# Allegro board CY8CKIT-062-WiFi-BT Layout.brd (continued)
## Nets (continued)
BT_REG_ON_P3_4: TP37.1 U1.M6(P3_4) U6.14(BT_REG_ON)
BT_UART_CTS: R202.2 TP42.1 U6.4(BT_UART_CTS)
BT_UART_RTS: R203.2 TP43.1 U6.5(BT_UART_RTS)
BT_UART_RXD: R200.2 TP40.1 U6.2(BT_UART_RXD)
BT_UART_TXD: R201.2 TP41.1 U6.3(BT_UART_TXD)
CAP_BUT0_P8_1: CSB1.3 R61.1
CAP_BUT1_P8_2: CSB2.3 R60.1
CAP_PROX_P8_0: J13.1 J13.2 R63.1 R64.1
CAP_SEG0_P8_3: CSS1.1(0) R53.1
CAP_SEG1_P8_4: CSS1.2(1) R52.1
CAP_SEG2_P8_5: CSS1.3(2) R47.1
CAP_SEG3_P8_6: CSS1.4(3) R58.1
CAP_SEG4_P8_7: CSS1.5(4) R59.1
CAP_TX_P1_0: CSB1.1 CSB1.2 CSB2.1 CSB2.2 CSS1.6(5) R62.2
CC1: C60.1 J10.A5(CC1) TVS2.1 U3.5(CC1)
CC2: C59.1 J10.B5(CC2) TVS2.2 U3.3(CC2)
CCG_12V_EN: R184.2 U3.35(P3.3) U31.4(EN)
CCG_LED: LED7.K(CATHODE) U3.34(P3.2)
CCG_O_EN: R84.2 U3.38(P3.6) U13.2(IN)
CCG_SWDCLK: TP36.1 U3.16(P2.1)
CCG_SWDIO: TP38.1 U3.15(P2.0)
CCG_VBUS_OUT: D8.K(CATHODE) D9.K(CATHODE) R154.1 U3.40(VBUS_P)
CCG_VCCD: C71.1 C72.1 U3.19(VCCD)
CCG_VDD: C68.1 C69.1 C70.1 U3.17(VDDD) U3.18(VDDIO)
CCG_VSYS: C8.1 C77.1 C79.1 D1.K(CATHODE) D2.K(CATHODE) R75.1 TP29.1 U3.20(VSYS)
CCG_XRES_L: C83.1 TP32.1 U3.26(XRES)
CE_L: C14.1 R4.2 R11.2 U3.10(P1.3) U19.4(C\E\)
CHG_L: R102.1 U19.13(C\H\G\)
DEV_USB_DM: J28.A7(DN1) J28.B7(DN2) U16.4(HSD1-)
DEV_USB_DP: J28.A6(DP1) J28.B6(DP2) U16.5(HDS1+)
DIGPOT_SCL: R155.2 U2.68(P2[5]) U27.2(SCL)
DIGPOT_SDA: R157.2 U2.1(P2[6]) U27.3(SDA)
ECO_P12_6: C99.1 R131.2 Y2.1
ECO_P12_7: C96.1 R126.2 Y2.2
FLASH_CS_P11_2: R134.2 R176.2 U4.C2(C\S\)
FRAM_CS_P11_0: R39.2 R173.2 U5.1(C\S\)
FRAM_VDD: C17.1 J26.1 R13.2 R17.2 R38.2 R39.1 U5.8(VDD)
HOST_USB_DM: J27.2(D-) U16.6(HSD2-)
HOST_USB_DP: J27.3(D+) U16.7(HSD2+)
I2C_SCL: J6.6 R30.1 R40.1 R141.1 U2.38(P12[0])
I2C_SCL_EC: R30.2 U3.37(P3.5)
I2C_SDA: J6.10 R29.1 R43.1 R150.1 U2.39(P12[1])
I2C_SDA_EC: R29.2 U3.36(P3.4)
IN_N: C84.1 R106.1 U21.3(-IN)
IUSB1: R1.1 R2.1 U3.7(P1.0) U19.17(IUSB1)
IUSB2: R6.1 R9.1 U3.8(P1.1) U19.16(IUSB2)
IUSB3: R5.1 R10.1 U3.9(P1.2) U19.14(IUSB3)
J1_3V3: J1.5 U28.4(OUT)
J1_5V0: J1.4 U29.4(OUT)
J2_P9_3: J2.8 R162.2
J18_P7_0: J18.6 R181.2
J18_P7_3: J18.5 R146.1
J18_P7_4: J18.4 R178.2
J18_P7_5: J18.3 R179.2
J18_P7_6: J18.2 R180.2
J18_P7_7: J18.1 R142.2
J18_P11_0: J18.8 R175.2
J18_P11_2: J18.7 R177.2
J19_P1_0: J19.5 R174.2
J19_P12_4: J19.10 R74.2
J19_P12_5: J19.9 R73.2
J19_P12_6: J19.8 R135.2
J19_P12_7: J19.6 R120.2
J20_P8_0: J20.1 R64.2
J20_P8_1: J20.2 R172.2
J20_P8_2: J20.3 R166.2
J20_P8_3: J20.4 R153.2
J20_P8_4: J20.5 R152.2
J20_P8_5: J20.6 R149.2
J20_P8_6: J20.7 R158.2
J20_P8_7: J20.8 R160.2
KP2_SWCLK: R183.2 U2.47(P12[3])
KP2_SWD_RST_L: R182.2 U2.3(P12[4])
KP2_SWDIO: R194.2 U2.46(P12[2])
KP_PMIC_EN: R197.1 U2.2(P2[7]) U12.2(IN)
KP_PMIC_EN_OUT: R80.1 SW7.5 U12.4(OUT) U27.1(W\P\)
LPO_IN_32KHZ: U6.37(LPO_IN(32KHZ)) U11.3(OUT)
P0_0: C86.1 U1.E3(P0.0) Y1.1
P0_1: C85.1 U1.E2(P0.1) Y1.2
P0_2: J4.8 U1.E1(P0.2)
P0_3: R18.1 U1.F3(P0.3)
P0_4: R67.1 R68.2 R133.1 SW2.B(1) U1.F2(P0.4)
P0_5: U1.G3(P0.5) U20.2(IN)
P1_0: R62.1 R174.1 U1.G2(P1.0)
P1_1: R8.2 U1.G1(P1.1)
P1_2: J19.4 U1.H3(P1.2)
P1_3: J19.3 U1.H2(P1.3)
P1_4: J19.2 U1.H1(P1.4)
P1_5: J19.1 R27.1 U1.J3(P1.5)
P2_0: R122.1 U1.M2(P2_0)
P2_1: R32.1 U1.N2(P2_1)
P2_2: R128.1 U1.L3(P2_2)
P2_3: R132.1 U1.M3(P2_3)
P2_4: R36.1 U1.N3(P2_4)
P2_5: R28.1 U1.N1(P2_5)
P3_0: R201.1 U1.L5(P3_0)
P3_1: R200.1 U1.M5(P3_1)
P3_2: R202.1 U1.N5(P3_2)
P3_3: R203.1 U1.L6(P3_3)
P4_1: J21.1 U1.M7(P4_1)
P5_0: J4.1 R159.2 U1.N7(P5.0)
P5_1: J4.2 R156.2 U1.L8(P5.1)
P5_2: J4.3 R93.1 R204.2 U1.M8(P5.2)
P5_3: J4.4 R88.1 U1.N8(P5.3)
P5_4: J4.5 U1.L9(P5.4)
P5_5: J4.6 U1.M9(P5.5)
P5_6: J4.7 U1.N9(P5.6)
P5_7: J21.3 U1.N10(P5.7)
P5LP0_1: J6.4 U2.49(P0[1])
P5LP0_2: J7.1 U2.50(P0[2])
P5LP0_3: J7.3 U2.51(P0[3])
P5LP0_5: TP25.1 U2.30(P3[1]) U2.54(P0[5]) U25.10(OUT)
P5LP0_6: SH1.2 U2.37(P3[7]) U2.55(P0[6])
P5LP0_7: J7.5 U2.56(P0[7])
P5LP1_2: SW3.1 SW3.2 U2.13(P1[2])
P5LP1_3: R56.1 U2.14(P1[3])
P5LP1_4: R54.1 U2.15(P1[4])
P5LP1_5: R55.1 U2.16(P1[5])
P5LP2_0: U2.62(P2[0])
P5LP2_2: U2.64(P2[2])
P5LP2_3: U2.65(P2[3])
P5LP2_4: U2.66(P2[4])
P5LP3_0: J6.8 U2.29(P3[0])
P5LP3_4: J6.11 U2.33(P3[4])
P5LP3_5: J6.12 U2.34(P3[5])
P5LP3_6: J6.15 U2.36(P3[6])
P5LP15_0: SW4.1 SW4.2 U2.27(P15[0])
P5LP15_4: J7.9 U2.60(P15[4])
P5LP_SIO_VREF: R119.2 R123.1 U2.48(P0[0])
P5LP_SSEL_P12_4: R83.2 U17.5(A3)
P5LP_SWDCLK: J7.8 U2.12(P1[1])
P5LP_SWDIO: J7.10 U2.11(P1[0])
P5LP_USB_DM: J10.A7(DN1) J10.B7(DN2) R34.1 TVS2.5
P5LP_USB_DP: J10.A6(DP1) J10.B6(DP2) R35.1 TVS2.4
P5LP_VCCA: C40.1 U2.42(VCCA)
P5LP_VCCD: C30.2 C132.1 U2.26(VCCD#26) U2.57(VCCD#57)
P5LP_VDD: C32.1 C34.1 C56.2 C106.1 C107.1 C113.1 C115.1 C116.1 C118.1 C122.1 C123.1 C124.1 C125.1 C126.1 C127.1 C128.1 J6.1 J7.2 R37.1 R76.2 R124.2 R155.1 R157.1 U2.17(VDDIO1) U2.24(VDDD#24) U2.35(VDDIO3) U2.44(VDDA) U2.52(VDDIO) U2.59(VDDD#59) U2.67(VDDIO2) U12.1(OE) U17.20(VCCB) U23.1(OUT) U26.4(EN)
P5LP_XRES_L: J7.6 U2.10(X\R\E\S\)
P6_0: J3.10 R141.2 U1.M10(P6.0)
P6_1: J3.9 R150.2 U1.L10(P6.1)
P6_2: J2.15 U1.L11(P6.2)
P6_3: J2.17 R145.2 U1.M11(P6.3)
P6_4: J11.6 J12.6 U1.N11(P6.4)
P6_5: J11.8 J12.8 U1.M12(P6.5)
P6_6: R192.1 U1.N12(P6.6)
P6_7: R191.1 U1.M13(P6.7)
P6_PMIC_EN_OUT: R103.1 SW7.7 U20.4(OUT)
P6_VDD: C50.1 C55.1 C82.2 C108.1 C112.1 J1.7 J14.6(7) J26.2 L7.1 Q4.3(D) R12.1 R13.1 R40.2 R43.2 R104.1 R148.2 R196.2 TP21.1 U8.4(OUT) U17.1(VCCA) U22.5(VCC) U24.3(IN) U25.2(IN+#2) U25.3(IN+#3)
P7_0: R181.1 R189.1 U1.L13(P7.0)
P7_1: C33.2 U1.L12(P7.1)
P7_2: C31.1 U1.K13(P7.2)
P7_3: C29.1 R146.2 U1.N13(P7.3)
P7_4: R178.1 R186.1 U1.K11(P7.4)
P7_5: R179.1 R187.1 U1.J13(P7.5)
P7_6: R180.1 R188.1 U1.J12(P7.6)
P7_7: C27.2 R142.1 U1.J11(P7.7)
P8_0: R63.2 U1.H13(P8.0)
P8_1: R61.2 R172.1 U1.H12(P8.1)
P8_2: R60.2 R166.1 U1.H11(P8.2)
P8_3: R53.2 R153.1 U1.G13(P8.3)
P8_4: R52.2 R152.1 U1.G12(P8.4)
P8_5: R47.2 R149.1 U1.G11(P8.5)
P8_6: R58.2 R158.1 U1.F13(P8.6)
P8_7: R59.2 R160.1 U1.F12(P8.7)
P9_0: J2.2 U1.E11(P9.0)
P9_1: J2.4 U1.E12(P9.1)
P9_2: J2.6 U1.E13(P9.2)
P9_3: R161.1 R162.1 U1.F11(P9.3)
P9_4: J2.10 U1.D13(P9.4)
P9_5: J2.12 U1.D12(P9.5)
P9_6: J2.16 U1.D11(P9.6)
P9_7: J2.18 U1.C13(P9.7)
P10_0: J2.1 U1.C12(P10.0)
P10_1: J2.3 U1.A11(P10.1)
P10_2: J2.5 U1.B11(P10.2)
P10_3: J2.7 U1.C11(P10.3)
P10_4: J2.9 U1.A10(P10.4)
P10_5: J2.11 U1.B10(P10.5)
P10_6: J2.13 U1.C10(P10.6)
P10_7: J21.5 U1.A9(P10.7)
P11_0: R173.1 R175.1 U1.B9(P11.0)
P11_1: R19.2 U1.C9(P11.1)
P11_2: R176.1 R177.1 U1.A8(P11.2)
P11_3: R17.1 U1.B8(P11.3) U4.D4(H\O\L\D\/IO3) U5.7(R\E\S\E\T/IO3)
P11_4: R38.1 U1.C8(P11.4) U4.C4(W\P\/IO2) U5.3(W\P\/IO2)
P11_5: U1.A7(P11.5) U4.D2(SO/IO1) U5.2(SO/IO1)
P11_6: U1.B7(P11.6) U4.D3(SI/IO0) U5.5(SI/IO0)
P11_7: U1.C7(P11.7) U4.B2(SCK) U5.6(SCK)
P12_0: J3.4 J5.4 J14.2 R77.1 U1.A6(P12.0)
P12_1: J3.5 J5.1 J14.3 R85.1 U1.B6(P12.1)
P12_2: J3.6 J5.3 J14.4 R81.1 U1.C6(P12.2)
P12_3: J3.3 U1.A5(P12.3)
P12_4: R74.1 R83.1 U1.B5(P12.4)
P12_5: R73.1 R82.1 U1.C5(P12.5)
P12_6: R131.1 R135.1 U1.A4(P12.6)
P12_7: R120.1 R126.1 U1.B4(P12.7)
P13_0: J3.1 U1.B1(P13.0)
P13_1: J3.2 U1.A3(P13.1)
P13_2: J21.2 R72.2 U1.B3(P13.2)
P13_3: J21.4 R71.1 U1.B2(P13.3)
P13_4: J21.6 R70.1 U1.C2(P13.4)
P13_5: J21.8 U1.C1(P13.5)
P13_6: J2.19 R45.2 U1.D3(P13.6)
P13_7: J2.20 R31.1 U1.D2(P13.7)
PMIC_EN: SW7.6 U9.3(EN) U10.3(EN)
PMOD_SSEL_P12_5: J14.1 R82.2
SDIO_CLK: R108.2 R113.1 U6.20(SDIO_CLK)
SDIO_CMD: R99.2 U6.22(SDIO_CMD)
SDIO_DATA0: R110.2 R115.1 U6.24(SDIO_DATA0)
SDIO_DATA1: R111.2 R116.1 U6.26(SDIO_DATA1)
SDIO_DATA2: R112.2 R117.1 U6.23(SDIO_DATA2)
SDIO_DATA3: R109.2 R114.1 U6.25(SDIO_DATA3)
SHIELD: CAP_SH1.1(SH) R44.1 R45.1 R145.1
SPI_MISO: J6.9 U2.4(P12[5]) U17.17(B2)
SPI_MOSI: J6.3 U2.28(P15[1]) U17.19(B0)
SPI_SCLK: J6.5 U2.40(P15[2]) U17.18(B1)
SPI_SSEL: J6.7 U2.41(P15[3]) U17.16(B3)
SWD_RST_L: J1.6 J5.5 J11.10 J12.10 R182.1 R190.2
TCLK_SWCLK: J11.4 J12.4 R183.1 R191.2
TMS_SWDIO: J11.2 J12.2 R192.2 R194.1
TRACECLK: J12.12 R189.2
TRACEDATA_0: J12.14 R161.2
TRACEDATA_1: J12.16 R188.2
TRACEDATA_2: J12.18 R187.2
TRACEDATA_3: J12.20 R186.2
TS: R94.2 R95.1 TP7.1 U19.5(TS)
UART_CTS: J6.2 U2.61(P15[5]) U17.14(B5)
UART_RTS: J7.7 U2.18(P1[6]) U17.15(B4)
UART_RX: J6.13 R156.1 U2.21(P12[7])
UART_TX: J6.14 R159.1 U2.20(P12[6])
USB_DEV_VBUS_DET: R70.2 R107.1 U22.4(OUT)
USB_DM: U1.L1(USBDM) U16.2(D-)
USB_DP: U1.L2(USBDP) U16.1(D+)
USB_HOST_EN: R72.1 R79.1 R90.2 U14.2(A) U16.10(S)
USB_INT_L: R71.2 R91.2 U15.3(FLG)
USB_TC_PWR_SENSE: C119.2 C120.1 Q1.5(D1#5) Q1.6(D1#6) R154.2 U3.39(OC)
USB_V_SENSE: R33.2 R37.2 U2.19(P1[7])
VBACKUP: C19.1 C25.1 R66.1 R67.2 R86.2 SW7.2 U1.D1(VBACKUP) U20.1(OE)
VBUCK1: C98.1 R129.1 U1.K3(VBUCK1)
VDRV: C73.1 LED6.A(ANODE) R95.2 U19.3(DRV)
VREF: C42.1 J3.8 U1.B13(VREF)
VRF: C23.1 TP5.1 U1.K1(VRF)
VTARG: J8.2 L4.1 L5.1 L6.1 R151.2 U21.1(+IN)
VTARG_BUF: C80.2 C84.2 C129.1 R106.2 U7.4(EN) U21.4(OUT) U26.3(IN)
VTARG_IN: D4.A(ANODE) J12.11 J12.13 R11.1
VTARG_MEAS: R130.2 R136.2 U2.32(P3[3])
VTARG_MON: R123.2 R130.1 U26.1(OUT)
VTARG_REF: C147.1 J11.1 J12.1 Q3.3(D) R196.1 TVS4.K
WL_GPIO_1: R20.1 TP16.1 U6.18(WL_GPIO_1)
WL_GPIO_2: TP11.1 U6.17(WL_GPIO_2)
WL_GPIO_4: TP19.1 U6.15(WL_GPIO_4)
WL_HOST_WAKE_P2_7: R133.2 TP34.1 U1.N4(P2_7) U6.27(WL_HOST_WAKE)
WL_JTAG_TCK: J25.9 R113.2
WL_JTAG_TDI: J25.3 R116.2
WL_JTAG_TDO: J25.5 R117.2
WL_JTAG_TMS: J25.7 R115.2
WL_JTAG_TRSTN: J25.1 R114.2
WL_REG_ON_P2_6: R89.1 TP33.1 U1.M4(P2_6) U6.28(WL_REG_ON)
WL_VBAT: C11.1 C12.1 C53.1 L3.2 TP4.1 U6.30(VBAT) U11.1(S\T\) U11.4(VCC)
WL_VDDIO: C5.1 C54.1 L7.2 R20.2 R21.1 R22.1 R23.1 R24.1 R25.1 R89.2 R96.1 TP1.1 U6.36(V_O)
XRES_L: C121.1 R147.2 R190.1 SW1.B(1) U1.F1(XRES)
N17133469: C97.1 U2.31(P3[2])
N17133474: C130.1 U2.53(P0[4])
N17133557: R35.2 U2.22(P15[6] D+)
N17133559: R34.2 U2.23(P15[7] D-)
N17715190: R164.1 U30.14(EN)
N17715216: C143.2 U30.3(VAUX)
N17715264: R171.2 U30.2(PG)
N17715329: L10.1 U30.11(L1)
N17715335: L10.2 U30.9(L2)
N17734371: C28.1 R26.2 U3.31(VBUS)
N17831172: Q2.2(S) Q3.2(S) Q4.2(S) R193.1
N17831185: D10.K(CATHODE) Q2.1(G) R193.2
N17831187: Q2.3(D) Q4.1(G) R195.2
N18060252: C142.2 R165.1 R169.2 U30.5(FB)
N18103700: C67.1 U19.1(PMID)
N18103720: C9.1 L8.1 U19.23(SW#23) U19.24(SW#24)
N18103734: C9.2 U19.2(BOOT)
N18103773: R92.1 R98.2 U19.15(VDPM)
N18103970: R105.1 U19.12(ISET)
N18115594: R46.2 R50.1 R51.2 U10.4(ADJ)
N18115805: R48.1 SW5.1
N18115822: R51.1 SW5.3
N18115824: SW5.4 U27.7(RH)
N18116972: LED6.K(CATHODE) R102.2
N18117036: LED4.A(ANODE) R57.2
N18205136: R137.2 R139.1 R140.2 R144.1
N18205137: Q1.4(G1) R143.2
N18205161: Q1.1(S2) Q1.3(S1) R139.2 TP39.1
N18205190: Q1.2(G2) R138.2
N18323131: D9.A(ANODE) U31.9(VOUT#9) U31.10(VOUT#10)
N18323163: R185.2 U31.5(ILIM)
N18323191: C146.2 U31.3(SS)
N18323606: R87.1 U13.1(GND)
N18323726: C49.1 J16.2 U13.3(OUT)
N18429699: R100.1 R104.2 U17.11(O\E\)
N18439299: L9.1 U1.J2(VIND1)
N18439327: L9.2 U1.K2(VIND2)
N18453045: C75.1 R97.2 U14.4(Y) U15.4(EN)
N18482506: R25.2 R32.2 R111.1
N18482508: R24.2 R109.1 R132.2
N18482512: R22.2 R112.1 R128.2
N18482514: R36.2 R96.2 R99.1
N18482516: R21.2 R28.2 R108.1
N18482684: R23.2 R110.1 R122.2
N18528852: L2.1 U6.34(SR_VLX)
N18619822: C2.2 C4.1 L1.2 L12.1 L13.2
N18697642: LED7.A(ANODE) R75.2
N18699542: LED1.A(ANODE) R56.2
N18699562: LED2.A(ANODE) R54.2
N18699568: LED3.A(ANODE) R55.2
N18713395: C44.2 R49.2 U8.3(EN)
N18743253: R163.1 R168.2 U30.1(PS/SYNC)
N18777793: C91.1 R118.2 R125.2 U23.4(EN)
N18781968: R77.2 U17.2(A0)
N18781971: R81.2 U17.3(A1)
N18781974: R85.2 U17.4(A2)
N18782191: R88.2 U17.6(A4)
N18782194: R93.2 U17.7(A5)
N18810466: J8.1 R148.1 R151.1 U25.4(IN-#4) U25.5(IN-#5)
N18832502: LED5.2 LED8.A(ANODE) LED9.A(ANODE) R12.2
N18832516: LED8.K(CATHODE) R27.2
N18832538: LED9.K(CATHODE) R31.2
N18832599: LED5.4 R19.1
N18832601: LED5.3 R8.1
N18832603: LED5.1 R18.2
N18833732: R65.1 R66.2 SW2.A(2)
N18852351: C7.1 L2.2 U6.31(VIN_LDO)
N18903176: C103.1 SW7.3
N18920306: R41.1 R42.2 U9.4(ADJ)
N18985234: J28.B5(CC2) R199.2
N18985239: J28.A5(CC1) R198.2
N19031222: ANT1.1 C1.2 L1.1
N19038486: J29.I(IN) L13.1

Pads without a net: ANT1 2; J1 8; J5 2; J10 A2 A3 A8 A10 A11 B2 B3 B8 B10 B11; J12 7; J28 A2 A3 A8 A10 A11 B2 B3 B8 B10 B11; J29 O; NOREF 1; NOREF#6 1; NOREF#12 1; NOREF#18 1; TVS2 6; U2 6; U3 4 6 11 12 13 14 21 22 23 27 28 29 30; U4 A2 A3 A4 A5 B1 B5 C1 C3 C5 D1 D5 E1 E2 E3 E5; U13 4; U14 1; U17 8 9 12 13 21; U18 4; U19 10 11; U25 1 6 7 8; U31 7 8

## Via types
v1: diameter 0.5, hole 0.25, TOP to BOTTOM, 1092 vias
v2: diameter 0.3, hole 0.15, TOP to BOTTOM, 97 vias

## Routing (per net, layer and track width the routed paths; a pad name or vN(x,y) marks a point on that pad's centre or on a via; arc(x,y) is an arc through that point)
5V_OUT: length 12.9
  TOP w0.635: v1(24.23,19.37) 25.58,19.37 26.57,20.36 30.14,20.36 30.88,19.63 v1(32.99,19.63)
  BOTTOM w0.254: U29.1 v1(46.47,24.72) ; v1(48.36,22.93) 48.37,22.92 U29.3
  BOTTOM w0.381: R171.1 32.75,19.38 v1(32.99,19.63)
  BOTTOM w0.635: C141.2 v1(29.03,23.46)
  vias: v1(28.19,23.46)
GND: length 1145.4
  TOP w0.114: 89.48,34.05 89.46,34.03 89.46,34.01
  TOP w0.178: 45.31,33.9 45.3,33.89 U2.8 ; U2.7 45.28,33.49 45.39,33.6 ; U2.9 45.2,34.29 45.36,34.13 ; U2.43 38.01,34.29 v1(38.41,34.69)
  TOP w0.198: v1(38.18,33.5) 38.16,33.49 U2.45 ; v1(43.13,31.85) 43.13,32.36 43.46,32.69 U2.5 ; v1(43.13,35.15) 43.99,34.29 U2.9 ; v1(41.48,36.8) 41.04,37.24 U2.25 ; v1(39.83,31.85) 39.84,31.84 U2.58 ; U2.7 43.14,33.49 v1(43.13,33.5) 43.52,33.89 U2.8
  TOP w0.203: U6.45 124.65,55.2 U6.29 ; v1(124.74,52.06) 124.92,51.88 U6.19 ; v1(121.13,56.71) 121.3,56.55 U6.1 ; v1(122.99,57.99) 122.99,57.89 122.67,57.57 U6.40 ; U1.B12 v2(86.67,36.95) ; 124.92,58.27 U6.35 v1(124.92,56.58) ; U1.C3 v2(86.02,43.37) ; U2.63 41.84,29.45 42.16,29.13 42.16,27.9 v1(42.01,27.75) ; v1(121.39,57.98) 121.71,57.65 ; U1.K10 v2(80.9,38.25) ; J28.A12 104.9,64.96 104.93,65.09 104.93,65.17 104.93,65.25 104.9,65.38 104.9,65.77 J28.B1 ; U1.K4 v2(81.47,42.15) ; U1.D4 v2(84.8,42.15) ; U1.D10 v2(85.37,38.25)
  TOP w0.254: U8.2 48.83,32.82 48.84,32.81 ; U8.2 49.48,33.25 U8.H ; U8.2 48.17,33.25 48.16,33.24 ; J10.B12 5.45,54.97 J10.A1 7.63,54.97 v1(7.98,55.31) ; J28.A1 110.4,65.77 J28.B12 ; J28.A1 110.78,64.51 ; J28.A1 110.4,63.73 ; U7.2 74.14,47.82 U7.H ; 121.71,57.65 U6.42 ; v1(17.22,49.76) 17.24,49.74 U3.33 ; 104.34,64.36 104.75,64.36 J28.A12 ; J10.A12 7.47,49.47
  TOP w0.305: v1(49.73,33.44) U8.H
  TOP w0.381: C39.2 67.56,34.45 ; C39.2 66.78,33.64 ; C39.2 66.78,35.25 ; C39.2 65.99,34.45 ; C40.2 29.92,34.09 ; C40.2 29.92,32.87 v1(30.18,32.61) ; C40.2 29.34,33.5 ; J21.7 74.19,65 ; J21.7 73.1,66.09 ; J21.7 73.1,63.91 ; J21.7 72.01,65 ; 68.17,41.33 C31.2 ; C31.2 69.03,40.34 ; C31.2 69.03,42.31 ; C31.2 69.88,41.33 ; 127.33,69.32 J29.G2 126.6,70.05 ; C47.2 66.53,23.06 ; C47.2 64.91,23.06 ; C47.2 65.72,23.84 ; J3.7 25.86,66.09 ; J3.7 25.86,63.91 ; J3.7 26.95,65 ; J3.7 24.77,65 ; 129.46,51.88 v1(129.46,52.69) ; v1(129.46,52.69) 130.25,52.69 ; v1(129.46,52.69) 128.68,52.69 ; v1(129.46,52.69) 129.46,53.49 ; R33.1 47.4,42.14 v1(47.47,42.21) ; R33.1 46.7,41.55 ; R33.1 46.7,42.73 ; J7.4 3.35,11.88 ; J7.4 2.26,12.97 ; J7.4 2.26,10.79 ; J7.4 1.17,11.88 ; 124.55,54.57 U6.45 124.55,56.03 ; 2.27,4.9 J9.1 ; J9.1 4.74,4.9 ; J9.1 3.51,6.13 ; 41.53,16.74 J1.2 ; J1.2 42.62,15.65 ; J1.2 42.62,17.83 ; J1.2 43.71,16.74 ; 65.48,38.51 J5.6 ; J5.6 64.39,39.6 ; J5.6 66.57,39.6 ; J5.6 65.48,40.69 ; 54.64,2.1 J12.3 ; R14.1 11.8,49.33 C15.2 ; R14.1 11.81,48.73 ; R14.1 11.81,49.92 ; R14.1 v1(10.87,49.32) ; R2.2 39.73,56.56 v1(39.57,56.71) ; 40.08,15.65 J1.3 ; J1.3 40.08,17.83 ; J1.3 41.17,16.74 ; J19.7 25.8,68.72 ; J19.7 25.8,66.41 ; J19.7 24.65,67.56 ; J19.7 26.96,67.56 ; 55.46,32.69 C41.2 ; C41.2 54.66,33.47 ; C41.2 55.46,34.25 ; 55.91,2.1 J12.5 ; C1.1 128.74,65.73 ; C1.1 127.52,65.73 ; C1.1 128.13,66.33 ; C10.2 11.8,55.43 v1(11.99,55.62) ; C10.2 11.81,54.7 R3.1 ; C10.2 11.8,54.12 ; 65.58,3.48 J12.19 64.8,2.1 ; 70,31.23 SW5.2 ; SW5.2 70.93,30.4 ; SW5.2 71.86,31.23 ; SW5.2 70.93,32.07 ; 32.82,39.93 C32.2 ; C32.2 33.4,40.52 ; C32.2 33.39,39.92 C34.2 32.81,38.68 ; 51.82,43.79 TP12.1 ; TP12.1 52.91,44.88 ; TP12.1 54,43.79 ; TP12.1 52.91,42.7 ; C35.2 C36.2 ; C35.2 89.65,38.44 ; C35.2 90.25,39.04 ; C36.2 91.52,39.11 ; C36.2 v1(92.41,38.44) ; LED4.K 18.99,16.05 ; LED4.K 17.37,16.05 ; LED4.K 18.18,17.06 ; LED4.K 18.18,15.05 ; 78.84,2.1 J11.9 79.62,3.48 ; TP8.1 135.31,48.07 ; TP8.1 134.21,49.17 ; TP8.1 134.21,46.98 ; TP8.1 133.12,48.07 ; 14.04,55.39 C8.2 ; C8.2 14.04,56.57 ; C8.2 v1(13.28,55.98) ; v1(49.48,31.6) 49.51,31.56 C44.1 ; J29.G1 128.07,68.05 ; J29.G1 127.33,68.78 ; J29.G1 127.33,67.32 ; J29.G1 126.6,68.05 ; 123.78,65.72 C2.1 ; C2.1 125,65.72 ; C2.1 124.39,66.33 ; U5.4 108.33,38.31 ; U5.4 v1(107.77,36.54) ; U5.4 107.22,38.31 ; U5.4 107.77,39.52 ; LED2.K 18.18,23.59 ; LED2.K 18.18,21.58 ; LED2.K v1(16.59,22.59) ; LED2.K 18.99,22.59 ; 123.53,58.43 C5.2 123.53,59.61 ; SW4.3 15.91,10.39 ; SW4.3 15.91,9.28 ; SW4.3 15.15,9.84 ; SW4.3 16.66,9.84 ; U4.B3 113.87,40.02 ; U4.B3 113.46,39.61 ; U4.B3 113.87,39.21 ; v1(125.89,50.74) U6.21 ; 18.18,19.4 LED3.K ; LED3.K 17.37,20.41 ; LED3.K 18.99,20.41 ; LED3.K 18.18,21.42 ; TP28.1 24.18,7.69 ; TP28.1 23.09,6.6 ; TP28.1 22,7.69 ; TP28.1 23.09,8.78 ; v1(88.44,48.99) 88.32,48.87 C20.2 ; R198.1 111.46,62.64 ; R198.1 111.46,61.45 ; R198.1 112.04,62.04 ; 13.23,43.63 C28.2 ; C28.2 13.81,44.22 ; C28.2 13.81,43.04 ; 64.39,19.28 J2.14 ; J2.14 65.48,18.19 ; J2.14 65.48,20.37 ; J2.14 66.57,19.28 ; 128.41,57.22 C7.2 127.6,58 ; 42.73,3.54 SW1.A ; SW1.A 43.96,4.57 ; SW1.A 42.73,5.42 v1(43.38,6.07) ; SW1.A 41.5,4.57 ; 50.14,34.87 50.14,34.49 49.73,34.08 U8.H ; R10.2 41.99,50.86 ; R10.2 41.99,49.67 ; R10.2 42.57,50.27 ; 63.53,2.1 J12.17 ; SW3.3 16.16,26.69 ; SW3.3 v1(15.4,25.67) ; SW3.3 14.64,26.69 ; SW3.3 15.4,27.24 ; C24.2 C18.2 83.24,48.88 v1(83.03,49.09) ; C43.2 65.84,33.67 ; C43.2 65.25,34.25 ; C43.2 65.06,33.47 U9.2 62.66,33.47 ; LED1.K 18.18,19.24 ; LED1.K 17,18.23 v1(16.33,18.9) ; LED1.K 18.18,17.23 ; LED1.K 18.99,18.23 ; 123.6,70.05 J29.G3 ; J29.G3 125.06,70.05 ; J29.G3 124.33,69.32 ; 58.45,2.1 J12.9 ; 78.77,48.6 C21.2 v1(78.18,49.63) 78.22,49.67 C16.1 78.8,50.49 ; C15.2 11.22,50.67 ; C15.2 11.8,51.26 ; 71.03,38.19 C33.1 ; C33.1 70.17,39.17 ; C33.1 71.88,39.17 ; C33.1 71.03,40.15 ; J16.1 5.3,68.45 ; J16.1 2.83,68.45 ; J16.1 4.06,69.68 ; 77.95,29.41 R48.2 ; R48.2 77.36,29.98 ; R48.2 78.54,29.98 ; J29.G4 125.06,68.05 ; J29.G4 124.33,68.78 ; J29.G4 123.6,68.05 ; J29.G4 124.33,67.32 ; 21.48,3.02 J14.5 ; J14.5 22.57,4.11 ; J14.5 23.66,3.02 ; J14.5 22.57,1.93 ; 63.23,35.41 R42.1 63.8,36 ; 89.46,33.99 C42.2 90.07,33.39 ; 13.59,64.04 J15.2 ; J15.2 14.52,64.97 ; J15.2 13.59,65.9 ; J15.2 12.66,64.97 ; 123.05,52.57 U6.44 123.05,54.03 ; C30.1 v1(39.48,42.39) ; C30.1 40.34,43.17 ; C30.1 40.93,42.39 ; SW4.4 v1(21.03,9.84) ; SW4.4 20.06,10.39 ; SW4.4 19.3,9.84 ; SW4.4 20.06,9.28 ; C38.2 92.11,35.17 ; C29.2 69.88,43.48 ; C29.2 68.17,43.48 ; C29.2 69.03,44.47 ; C29.2 69.03,42.5 ; 80.38,47.96 C23.2 80.98,48.35 80.67,48.66 v1(80.67,48.74) ; 80.04,47.96 C22.2 79.45,48.57 ; v1(121.13,51.37) U6.12 121.71,50.92 ; 123.05,54.57 U6.43 ; 73.05,48.07 U7.H 74.57,48.07 v1(74.86,47.78) ; 4.8,21.49 J6.16 ; J6.16 3.71,22.59 ; J6.16 5.89,22.59 ; J6.16 4.8,23.68 ; 11.81,52.77 R3.1 ; R3.1 v1(11.07,53.36) ; C46.2 65.52,24.58 ; C46.2 64.94,23.99 ; C46.2 64.94,25.09 64.49,25.54 U10.2 64.49,27.17 64.52,27.2 ; 68.3,32.28 R46.1 68.89,31.72 ; 121.2,59.55 L11.2 120.62,58.95 ; v1(86.37,49.12) 85.78,48.54 C19.2 C25.2 ; 75.03,2.1 J11.3 ; 36.71,50.9 R9.2 37.29,50.26 ; 18.79,26.69 SW3.4 ; SW3.4 19.55,27.24 ; SW3.4 20.31,26.69 ; SW3.4 19.55,26.13 ; 131.49,52.9 v1(132.07,52.9) 132.07,52.31 ; 62.26,2.1 J12.15 ; C20.2 C26.2 ; C20.2 88.93,48.23 ; 44.91,52.72 R4.1 ; R4.1 44.15,53.31 v1(44.02,53.19) ; R4.1 44.91,53.91 ; 44.9,51.45 C14.2 ; C14.2 44.15,52.04 v1(44.02,52.17) ; C14.2 44.9,52.64 ; 77.57,2.1 J11.7 ; C26.2 88.93,46.96 ; C26.2 88.32,46.37 ; C17.2 v1(105.89,49) ; 124.55,54.03 U6.46 124.55,52.57 ; 50.22,37.72 TP20.1 ; TP20.1 51.08,38.58 ; TP20.1 50.22,39.45 ; 128.63,53.68 C11.2 128.04,53.1 ; 61.7,31.51 C45.2 60.91,30.7 ; 121.2,61.9 L12.2 ; L12.2 121.2,63.1 ; L12.2 120.62,62.5 ; 23.87,57.78 TP30.1 24.95,57.78 ; 121.29,57.22 U6.42 ; 90.25,34.56 C37.2 ; 76.3,2.1 J11.5
  TOP w0.508: C37.2 C38.2 91.52,34.47 v1(91.57,34.41) ; C11.2 127.6,53.68 v1(127.08,54.2)
  L02_GND w0.381: J19.7 26.96,67.56 ; J19.7 25.8,68.72 ; J19.7 25.8,66.41 ; J19.7 24.65,67.56 ; 12.66,64.97 J15.2 ; J15.2 13.59,64.04 ; J15.2 14.52,64.97 ; J15.2 13.59,65.9 ; 73.1,63.91 J21.7 ; J21.7 72.01,65 ; J21.7 74.19,65 ; J21.7 73.1,66.09 ; J2.14 65.48,20.37 ; J2.14 65.48,18.19 ; J2.14 66.57,19.28 ; J2.14 64.39,19.28 ; 63.53,2.1 J12.17 ; J3.7 26.95,65 ; J3.7 24.77,65 ; J3.7 25.86,63.91 ; J3.7 25.86,66.09 ; 64.39,39.6 J5.6 ; J5.6 66.57,39.6 ; J5.6 65.48,40.69 ; J5.6 65.48,38.51 ; 79.62,3.48 J11.9 78.84,2.1 ; TP20.1 50.75,38.58 ; TP20.1 49.68,38.58 ; TP20.1 50.22,38.05 ; TP20.1 50.22,39.11 ; 134.21,46.98 TP8.1 ; TP8.1 135.31,48.07 ; TP8.1 134.21,49.17 ; TP8.1 133.12,48.07 ; 62.26,2.1 J12.15 ; J1.2 42.62,17.83 ; J1.2 42.62,15.65 ; J1.2 41.53,16.74 ; J1.2 43.71,16.74 ; 77.57,2.1 J11.7 ; 65.58,3.48 J12.19 64.8,2.1 ; 84.42,58.23 J27.4 ; J27.4 86.53,58.23 ; J27.4 85.47,57.17 ; J27.4 85.47,59.29 ; TP12.1 54,43.79 ; TP12.1 52.91,44.88 ; TP12.1 51.82,43.79 ; TP12.1 52.91,42.7 ; 3.71,22.59 J6.16 ; J6.16 4.8,21.49 ; J6.16 5.89,22.59 ; J6.16 4.8,23.68 ; 23.09,6.6 TP28.1 ; TP28.1 24.18,7.69 ; TP28.1 22,7.69 ; TP28.1 23.09,8.78 ; TP30.1 24.41,58.31 ; TP30.1 23.88,57.78 ; TP30.1 24.94,57.78 ; TP30.1 24.41,57.25 ; 2.83,68.45 J16.1 ; J16.1 4.06,69.68 ; J16.1 5.3,68.45 ; J28.B1 105.41,65.82 ; J1.3 41.17,16.74 ; J1.3 40.08,17.83 ; J1.3 40.08,15.65 ; J1.3 38.99,16.74 ; 1.17,11.88 J7.4 ; J7.4 3.35,11.88 ; J7.4 2.26,10.79 ; J7.4 2.26,12.97 ; 76.3,2.1 J11.5 ; J14.5 23.66,3.02 ; J14.5 22.57,1.93 ; J14.5 21.48,3.02 ; J14.5 22.57,4.11 ; 55.91,2.1 J12.5 ; 4.98,55.52 5.4,55.1 J10.B12 5.4,54.46 ; 54.64,2.1 J12.3 ; 5.4,49.97 J10.B1 5.4,49.28 5.05,48.94 ; 58.45,2.1 J12.9 ; J9.1 3.51,6.13 ; J9.1 4.74,4.9 ; J9.1 2.27,4.9 ; 75.03,2.1 J11.3 ; 109.9,65.82 J28.B12
  L03_SIG w0.305: J10.B12 5.39,55.02 4.83,55.58
  L03_SIG w0.381: J6.16 5.89,22.59 ; J6.16 4.8,21.49 ; J6.16 4.8,23.68 ; J6.16 3.71,22.59 ; 22,7.69 TP28.1 ; TP28.1 23.09,8.78 ; TP28.1 24.18,7.69 ; TP28.1 23.09,6.6 ; 110.95,66.32 J28.B12 110.39,65.76 110.39,65.17 ; 50.22,38.05 TP20.1 ; TP20.1 50.22,39.11 ; TP20.1 50.75,38.58 ; J21.7 74.19,65 ; J21.7 72.01,65 ; J21.7 73.1,63.91 ; 2.27,4.9 J9.1 ; J9.1 3.51,6.13 ; J9.1 4.74,4.9 ; J16.1 5.3,68.45 ; J16.1 4.06,69.68 ; J16.1 2.83,68.45 ; 25.8,66.41 J19.7 ; J19.7 24.65,67.56 ; J19.7 25.8,68.72 ; J19.7 26.96,67.56 ; 75.03,2.1 J11.3 ; 13.59,64.04 J15.2 ; J15.2 12.66,64.97 ; J15.2 13.59,65.9 ; J15.2 14.52,64.97 ; 25.86,63.91 J3.7 ; J3.7 24.77,65 ; J3.7 25.86,66.09 ; J3.7 26.95,65 ; 79.62,3.48 J11.9 78.84,2.1 ; 42.62,15.65 J1.2 ; J1.2 43.71,16.74 ; J1.2 42.62,17.83 ; J1.3 40.08,17.83 ; J1.3 40.08,15.65 ; J1.3 38.99,16.74 ; 58.45,2.1 J12.9 ; J14.5 23.66,3.02 ; J14.5 22.57,1.93 ; J14.5 21.48,3.02 ; J14.5 22.57,4.11 ; 4.93,48.95 5.4,49.42 J10.B1 5.4,49.42 5.94,49.96 ; 65.48,18.19 J2.14 ; J2.14 64.39,19.28 ; J2.14 65.48,20.37 ; 85.47,57.17 J27.4 ; J27.4 85.47,59.29 ; J27.4 84.42,58.23 ; 65.48,38.51 J5.6 ; J5.6 65.48,40.69 ; J5.6 66.57,39.6 ; 104.37,66.24 104.78,65.82 J28.B1 ; 24.41,57.25 TP30.1 ; TP30.1 24.41,58.31 ; TP30.1 23.88,57.78 ; 2.26,10.79 J7.4 ; J7.4 2.26,12.97 ; J7.4 3.35,11.88 ; J7.4 1.17,11.88 ; TP8.1 135.31,48.07 ; TP8.1 133.12,48.07 ; TP8.1 134.21,46.98 ; TP8.1 134.21,49.17 ; 5.4,54.46 J10.B12 ; 77.57,2.1 J11.7 ; TP12.1 54,43.79 ; TP12.1 52.91,44.88 ; TP12.1 51.82,43.79 ; TP12.1 52.91,42.7 ; 76.3,2.1 J11.5 ; 54.64,2.1 J12.3 ; 55.91,2.1 J12.5
  L04_MIX w0.381: 76.3,2.1 J11.5 ; 2.26,10.79 J7.4 ; J7.4 2.26,12.97 ; J7.4 1.17,11.88 ; J7.4 3.35,11.88 ; J27.4 85.47,59.29 ; 41.53,16.74 J1.2 ; J1.2 42.62,15.65 ; J1.2 43.71,16.74 ; 3.71,22.59 J6.16 ; J6.16 4.8,21.49 ; J6.16 5.89,22.59 ; J6.16 4.8,23.68 ; 24.65,67.56 J19.7 ; J19.7 25.8,68.72 ; J19.7 26.96,67.56 ; J19.7 25.8,66.41 ; 77.57,2.1 J11.7 ; J21.7 73.1,66.09 ; J21.7 73.1,63.91 ; J21.7 74.19,65 ; J21.7 72.01,65 ; J9.1 3.51,6.13 ; J1.3 41.17,16.74 ; J1.3 40.08,15.65 ; J1.3 38.99,16.74 ; 64.39,19.28 J2.14 ; J2.14 65.48,18.19 ; J2.14 65.48,20.37 ; TP20.1 50.75,38.58 ; TP20.1 50.22,38.05 ; TP20.1 50.22,39.11 ; TP20.1 49.68,38.58 ; 5.4,54.46 J10.B12 ; 58.45,2.1 J12.9 ; 12.66,64.97 J15.2 ; J15.2 13.59,64.04 ; J15.2 14.52,64.97 ; J15.2 13.59,65.9 ; 23.88,57.78 TP30.1 ; TP30.1 24.41,58.31 ; TP30.1 24.94,57.78 ; TP30.1 24.41,57.25 ; 75.03,2.1 J11.3 ; 79.62,3.48 J11.9 78.84,2.1 ; 109.9,65.82 J28.B12 ; 25.86,63.91 J3.7 ; J3.7 24.77,65 ; J3.7 26.95,65 ; J3.7 25.86,66.09 ; TP12.1 54,43.79 ; TP12.1 52.91,42.7 ; TP12.1 52.91,44.88 ; TP12.1 51.82,43.79 ; 55.91,2.1 J12.5 ; J16.1 4.06,69.68 ; J16.1 5.3,68.45 ; J16.1 2.83,68.45 ; 54.64,2.1 J12.3 ; J10.B1 5.4,49.97
  L05_MIX w0.381: 86.53,58.23 J27.4 85.47,59.29 ; 50.22,38.05 TP20.1 ; TP20.1 50.22,39.11 ; TP20.1 50.75,38.58 ; TP20.1 49.68,38.58 ; 134.21,46.98 TP8.1 ; TP8.1 135.31,48.07 ; TP8.1 134.21,49.17 ; 109.9,65.82 J28.B12
  L06_SIG w0.381: 2.26,10.79 J7.4 ; J7.4 2.26,12.97 ; J7.4 3.35,11.88 ; J7.4 1.17,11.88 ; 54.64,2.1 J12.3 ; J28.B1 105.41,65.82 ; 79.62,3.48 J11.9 78.84,2.1 ; TP8.1 134.21,49.17 ; TP8.1 135.31,48.07 ; TP8.1 134.21,46.98 ; TP8.1 133.12,48.07 ; 49.68,38.58 TP20.1 ; TP20.1 50.22,39.11 ; TP20.1 50.22,38.05 ; TP20.1 50.75,38.58 ; 65.48,38.51 J5.6 ; J5.6 66.57,39.6 ; J5.6 64.39,39.6 ; 22,7.69 TP28.1 ; TP28.1 23.09,6.6 ; TP28.1 23.09,8.78 ; TP28.1 24.18,7.69 ; 64.39,19.28 J2.14 ; J2.14 66.57,19.28 ; J2.14 65.48,18.19 ; J2.14 65.48,20.37 ; J14.5 22.57,4.11 ; J14.5 23.66,3.02 ; J14.5 21.48,3.02 ; J14.5 22.57,1.93 ; J1.2 42.62,17.83 ; J1.2 41.53,16.74 ; J1.2 43.71,16.74 ; 52.91,42.7 TP12.1 ; TP12.1 52.91,44.88 ; TP12.1 51.82,43.79 ; TP12.1 54,43.79 ; J19.7 25.8,68.72 ; J19.7 25.8,66.41 ; J19.7 24.65,67.56 ; J19.7 26.96,67.56 ; 77.57,2.1 J11.7 ; 5.89,22.59 J6.16 3.71,22.59 ; 65.58,3.48 J12.19 64.8,2.1 ; 75.03,2.1 J11.3 ; 5.4,54.46 J10.B12 ; 62.26,2.1 J12.15 ; J1.3 41.17,16.74 ; J1.3 38.99,16.74 ; J1.3 40.08,17.83 ; TP30.1 24.94,57.78 ; TP30.1 24.41,58.31 ; TP30.1 23.88,57.78 ; TP30.1 24.41,57.25 ; 2.83,68.45 J16.1 ; J16.1 5.3,68.45 ; J16.1 4.06,69.68 ; J10.B1 5.4,49.97 ; 55.91,2.1 J12.5 ; 76.3,2.1 J11.5 ; J3.7 25.86,66.09 ; 74.19,65 J21.7 72.01,65 ; J9.1 4.74,4.9 ; J9.1 3.51,6.13 ; J9.1 2.27,4.9 ; 63.53,2.1 J12.17 ; 109.9,65.82 J28.B12 ; 58.45,2.1 J12.9
  L07_GND w0.381: 64.39,39.6 J5.6 ; J5.6 65.48,38.51 ; J5.6 66.57,39.6 ; J5.6 65.48,40.69 ; 54.64,2.1 J12.3 ; TP28.1 23.09,8.78 ; TP28.1 24.18,7.69 ; TP28.1 22,7.69 ; TP28.1 23.09,6.6 ; J27.4 85.47,59.29 ; J27.4 85.47,57.17 ; J27.4 86.53,58.23 ; J27.4 84.42,58.23 ; J7.4 3.35,11.88 ; J7.4 1.17,11.88 ; J7.4 2.26,12.97 ; J7.4 2.26,10.79 ; 13.59,64.04 J15.2 ; J15.2 13.59,65.9 ; J15.2 12.66,64.97 ; J15.2 14.52,64.97 ; 65.48,18.19 J2.14 ; J2.14 65.48,20.37 ; J2.14 64.39,19.28 ; J2.14 66.57,19.28 ; 21.48,3.02 J14.5 ; J14.5 22.57,4.11 ; J14.5 23.66,3.02 ; J14.5 22.57,1.93 ; 133.12,48.07 TP8.1 ; TP8.1 135.31,48.07 ; TP8.1 134.21,46.98 ; TP8.1 134.21,49.17 ; J16.1 4.06,69.68 ; J16.1 5.3,68.45 ; J16.1 2.83,68.45 ; 25.8,66.41 J19.7 ; J19.7 25.8,68.72 ; J19.7 24.65,67.56 ; J19.7 26.96,67.56 ; J21.7 73.1,66.09 ; J21.7 73.1,63.91 ; J21.7 72.01,65 ; J21.7 74.19,65 ; 109.9,65.82 J28.B12 ; 77.57,2.1 J11.7 ; TP20.1 50.75,38.58 ; TP20.1 50.22,39.11 ; TP20.1 50.22,38.05 ; TP20.1 49.68,38.58 ; 4.8,21.49 J6.16 ; J6.16 3.71,22.59 ; J6.16 5.89,22.59 ; J6.16 4.8,23.68 ; TP30.1 24.94,57.78 ; TP30.1 24.41,58.31 ; TP30.1 24.41,57.25 ; TP30.1 23.88,57.78 ; 79.62,3.48 J11.9 78.84,2.1 ; 75.03,2.1 J11.3 ; 40.08,15.65 J1.3 ; J1.3 38.99,16.74 ; J1.3 41.17,16.74 ; J1.3 40.08,17.83 ; J1.2 42.62,17.83 ; J1.2 42.62,15.65 ; J1.2 43.71,16.74 ; J1.2 41.53,16.74 ; TP12.1 54,43.79 ; TP12.1 51.82,43.79 ; TP12.1 52.91,42.7 ; TP12.1 52.91,44.88 ; J28.B1 105.41,65.82 ; 2.27,4.9 J9.1 ; J9.1 4.74,4.9 ; J9.1 3.51,6.13 ; 5.4,54.46 J10.B12 ; 76.3,2.1 J11.5 ; J3.7 25.86,66.09 ; J3.7 24.77,65 ; J3.7 26.95,65 ; J3.7 25.86,63.91 ; 58.45,2.1 J12.9 ; 62.26,2.1 J12.15 ; 65.58,3.48 J12.19 64.8,2.1 ; 55.91,2.1 J12.5 ; 63.53,2.1 J12.17 ; J10.B1 5.4,49.97
  BOTTOM w0.152: U30.15 31.65,21.09 31.31,21.44 v1(31.06,21.44)
  BOTTOM w0.198: U16.8 86.62,55.63 v1(86.89,55.9) ; v1(83.79,53.44) 83.85,53.44 84.34,53.93 U16.3 ; SH1.1 51.28,36.55 51.28,36.21 51.38,36.1 U25.9
  BOTTOM w0.203: 97.51,48.58 97.42,48.58 97.29,48.71 ; R199.1 v1(108.89,68.52)
  BOTTOM w0.254: v1(29.92,25.88) 30.53,25.27 30.53,25.22 ; U26.2 48.21,30.96 v1(47.96,30.71) ; U26.2 48.21,32.24 ; U26.2 48.59,31.61 ; v1(42.88,52.93) 43.03,53.09 43.03,53.43 ; 42.31,55.1 U19.20 42.31,52.49 v1(41.99,52.17) ; C93.2 v1(88.34,45.69) ; v1(31.19,25.88) 30.53,25.22 ; 30.53,25.22 U30.10 ; 43.03,53.43 43.31,53.71 U19.22 43.31,55.1 ; 43.03,53.43 42.81,53.66 U19.21 42.81,55.1 ; U24.2 118.31,40.36 v1(118.06,40.11) ; U31.6 8.5,13.65 v1(8.59,13.56) ; U31.6 8.12,14.63 ; U31.6 8.5,15.31 ; v1(32.72,20.93) 32.55,21.09 U30.15 31.93,20.74 ; U17.10 56.46,51.29 v1(56.72,51.03) ; v1(44.02,43.66) 43.77,43.41 U23.2 ; 29.42,20.69 U30.4 29.78,20.13 29.77,20.12 ; v1(28.25,21.42) 28.43,21.59 U30.6 29.64,21.59 29.79,21.44 v1(30.02,21.44)
  BOTTOM w0.279: 48.1,24.72 U29.2 47.72,25.35 ; 118.69,41.01 U24.2 118.31,41.64 ; U17.10 56.84,51.95 ; 50.01,25.35 U28.2 50.39,24.72
  BOTTOM w0.305: 81.92,56.85 81.91,56.85 R78.2
  BOTTOM w0.381: 90.78,55.61 C62.1 ; C62.1 90.12,56.2 v1(89.98,56.35) ; C62.1 90.78,56.79 ; C127.2 39.19,31.67 ; C127.2 39.78,31.09 ; C127.2 38.6,31.09 ; 133.97,37.95 R44.2 ; R44.2 135.53,37.95 ; R44.2 134.75,37.17 ; R44.2 134.75,38.73 ; 48.7,52.6 C73.2 ; C73.2 48.7,53.78 ; C73.2 v1(49.61,53.19) ; U14.3 v1(74.67,55.19) ; U14.3 74.67,56.99 ; U14.3 75.12,56.21 ; 44.13,34.94 C115.2 ; C115.2 43.56,35.53 ; C115.2 44.13,36.13 ; 89.52,53.92 C65.2 ; C65.2 89.52,55.83 ; C65.2 90.25,55.19 90.4,55.33 v1(90.4,55.42) ; 73.1,63.91 J21.7 ; J21.7 74.19,65 ; J21.7 73.1,66.09 ; v1(47.47,42.21) 47.38,42.21 47.07,42.52 R125.1 ; 6.58,60.77 C49.2 ; C49.2 7.59,61.68 ; C49.2 5.57,61.68 ; C49.2 6.58,62.59 ; 42.62,3.07 R195.1 ; R195.1 42.03,3.66 ; R195.1 44.35,3.66 v1(44.48,3.78) ; 46.79,23.82 U29.H 48.15,23.82 ; 10.81,56.96 C59.2 ; C59.2 10.81,58.15 ; C59.2 10.96,57.4 v1(10.96,56.74) ; 44.7,43.66 v1(44.02,43.66) 43.34,43.66 ; R100.2 57.05,50.27 ; R100.2 56.47,49.67 ; R100.2 56.47,50.86 ; C60.2 7.51,58.15 ; C60.2 v1(6.43,57.56) ; C60.2 7.51,56.96 ; 36.64,44.47 R119.1 ; R119.1 36.64,45.65 ; R119.1 36.07,45.06 ; 115.5,37.05 C111.2 ; C111.2 117.06,37.05 ; C111.2 116.28,36.24 ; C111.2 116.28,37.85 ; 22.57,1.93 J14.5 ; J14.5 22.57,4.11 ; J14.5 23.66,3.02 ; J14.5 21.48,3.02 ; R169.1 v1(25.35,20.42) ; R169.1 26.21,19.83 ; R169.1 26.21,21.01 ; 38.98,55.86 C64.2 ; C64.2 v1(39.57,56.71) ; C64.2 40.17,55.86 ; 6.98,8.61 R185.1 ; R185.1 7.57,8.03 ; R185.1 8.16,8.61 ; 41.99,47.14 R105.2 ; R105.2 42.58,47.72 ; R105.2 41.26,47.72 v1(41,47.69) ; 106.02,56.22 U12.3 ; U12.3 106.33,56.78 106.73,56.38 v1(107.05,56.38) ; U12.3 105.14,56.78 ; v1(118.06,40.11) 118.74,40.11 ; C109.2 115.35,37.56 ; C109.2 114.17,37.56 ; C109.2 v1(114.76,36.68) ; C63.2 38.05,57.56 ; C63.2 v1(36.91,56.75) ; C63.2 38.83,56.75 ; C63.2 38.05,55.95 ; 75.03,2.1 J11.3 ; v1(57.23,59.89) C55.2 ; C55.2 57.82,59.03 ; C55.2 C56.1 ; R168.1 v1(35.13,19.66) ; R168.1 35.71,20.42 ; R168.1 35.13,21.01 ; C136.2 28.29,26.38 ; C136.2 27.51,27.18 ; C136.2 26.73,26.38 ; v1(25.98,56.62) 25.86,56.49 R84.1 25.86,55.01 ; C83.2 16.92,49.68 ; 34.24,41.29 C97.2 ; C97.2 33.66,41.88 ; C97.2 34.24,42.48 ; 114.03,64.31 C48.2 ; C48.2 113.44,64.89 ; C48.2 114.62,64.89 ; C131.2 63.57,26.98 ; C131.2 62.99,26.39 ; C131.2 63.57,25.75 ; C141.1 29.62,25.51 ; C141.1 29.03,26.09 ; C141.1 28.44,25.51 ; C89.2 9.76,45.36 v1(9.76,44.64) ; C89.2 10.36,45.06 ; C89.2 10.36,46.87 ; C89.2 9.36,45.96 ; C89.2 11,45.33 v1(11,44.68) ; C128.2 38.51,31.1 ; C128.2 37.33,31.1 ; C128.2 37.92,31.68 ; R90.1 90.09,52.65 ; R90.1 89.51,53.24 ; R90.1 89.36,52.49 89.36,52.01 ; 11.42,12.69 C145.1 ; C145.1 12.01,13.3 v1(11.79,13.53) ; C145.1 12.61,12.69 ; 31.4,53.45 C74.1 30.66,52.86 v1(30.43,52.63) ; 15.46,33.04 C119.1 ; C119.1 v1(15.46,34.59) ; C119.1 16.03,33.63 ; R167.1 36.51,21.01 ; R167.1 35.94,20.42 ; R167.1 36.51,19.53 v1(36.64,19.41) ; 35.19,60.55 C52.2 ; C52.2 37.15,60.55 ; C52.2 v1(36.17,62.08) ; C52.2 36.17,59.37 ; C121.2 76.94,30.31 ; C121.2 76.35,29.73 ; C121.2 75.76,30.31 ; 39.92,31.13 C123.2 ; C123.2 41.1,31.13 ; C123.2 40.51,31.7 ; 79.62,3.48 J11.9 78.84,2.1 ; 48.72,53.87 C67.2 ; C67.2 v1(49.61,54.46) ; C67.2 48.72,55.05 ; 44.4,31.68 C125.2 43.81,31.1 ; J1.3 40.08,17.83 ; J1.3 40.08,15.65 ; J1.3 41.17,16.74 ; C94.2 115.86,44.43 ; C94.2 114.67,44.43 ; C94.2 v1(115.27,45.2) ; 12.69,12.68 C144.1 13.28,13.3 v1(12.93,13.66) ; 31.41,51.04 C78.1 30.66,51.64 30.65,51.63 v1(30.45,51.63) ; 8.05,13.08 U31.EPAD 10.96,13.08 ; 133.12,48.07 TP8.1 ; TP8.1 134.21,46.98 ; TP8.1 135.31,48.07 ; TP8.1 134.21,49.17 ; C76.1 75.29,52.39 v1(75.41,52.52) 75.54,52.39 C75.2 76.43,52.98 ; C76.1 74.41,51.8 ; C76.1 74.41,52.98 ; R170.1 46.95,20.63 ; R170.1 47.52,20.04 ; R170.1 v1(46.95,19.28) ; 10.59,56.06 TVS2.3 10.14,56.85 ; 42.54,31.09 C126.2 ; C126.2 43.13,31.67 ; C126.2 43.72,31.09 ; 44.14,36.21 C113.2 ; C113.2 43.56,36.8 ; C113.2 44.14,37.4 ; 25.52,25.7 C133.2 ; C133.2 25.52,27.51 ; C133.2 26.53,26.6 ; C133.2 24.51,26.6 ; J3.7 26.95,65 ; J3.7 25.86,66.09 ; J3.7 24.77,65 ; J3.7 25.86,63.91 ; R87.2 25.86,54.92 ; R87.2 25.27,54.33 ; R87.2 25.86,53.57 26.24,53.19 v1(26.24,53.19) ; C66.2 82.39,53.61 ; C66.2 80.37,53.61 ; C66.2 81.38,54.31 ; C66.2 81.38,52.9 ; C117.2 79.98,35.36 ; C117.2 79.37,34.77 ; C117.2 79.98,34.18 ; C147.2 71.13,4.55 ; C147.2 70.54,5.13 ; C147.2 v1(69.67,4.55) ; J6.16 4.8,23.68 ; J6.16 3.71,22.59 ; J6.16 4.8,21.49 ; J6.16 5.89,22.59 ; C96.2 93.17,44.63 ; C96.2 93.76,44.05 ; C96.2 92.58,44.05 ; C53.2 130.64,59.67 ; C53.2 130.05,59.09 ; C53.2 129.46,59.67 ; 81.36,57.65 81.61,57.39 R78.2 C58.2 83.84,57.39 84.68,58.23 J27.4 ; C108.2 120.18,37.55 ; C108.2 118.99,37.55 ; C108.2 v1(119.58,36.77) ; J19.7 26.96,67.56 ; J19.7 24.65,67.56 ; J19.7 25.8,68.72 ; J19.7 25.8,66.41 ; 38.59,8.58 D10.A ; D10.A v1(37.31,9.21) ; D10.A 39.42,9.21 ; 41.53,16.74 J1.2 ; TP20.1 50.22,39.45 ; TP20.1 49.35,38.58 ; TP20.1 50.22,37.72 ; TP20.1 51.08,38.58 ; 44.82,47.72 C87.2 ; C87.2 45.42,47.14 ; C87.2 46.01,47.72 ; 2.26,10.79 J7.4 ; J7.4 1.17,11.88 ; J7.4 3.35,11.88 ; J7.4 2.26,12.97 ; C118.2 37.47,34.63 ; C118.2 37.47,33.44 ; C118.2 38.05,34.04 ; C70.2 C71.2 16.55,53.41 C72.2 14.71,53.41 ; C70.2 17.83,52.84 ; C70.2 19.08,53.42 C69.2 ; 121.11,36.11 C112.2 ; C112.2 121.11,37.73 ; C112.2 120.33,36.92 ; C112.2 121.89,36.92 ; 33.63,25.54 C137.2 ; C137.2 33.63,27.16 ; C137.2 32.85,26.35 ; C54.2 122.89,59.02 ; C86.2 83.39,48.83 ; C86.2 83.39,47.64 ; C86.2 82.8,48.23 ; C146.1 10.7,8.61 ; C146.1 10.11,8.03 ; C146.1 9.52,8.61 ; 37.8,37.11 R136.1 ; R136.1 37.2,37.68 ; R136.1 38.39,37.68 ; TP28.1 23.09,8.78 ; TP28.1 23.09,6.6 ; TP28.1 24.18,7.69 ; TP28.1 22,7.69 ; C140.1 32.67,25.51 ; C140.1 32.08,26.09 ; C140.1 31.49,25.51 ; C82.1 89.35,50.73 ; C82.1 89.35,49.55 ; C82.1 88.77,50.14 ; 16.14,30.86 C120.2 ; C120.2 16.14,32.67 v1(16.48,33.02) ; C120.2 15.23,31.87 ; C120.2 17.04,31.87 ; J16.1 5.3,68.45 ; J16.1 4.06,69.68 ; J16.1 2.83,68.45 ; 79.37,36.04 C114.2 79.98,35.45 ; 43.05,47.72 C88.2 ; C88.2 44.39,47.72 44.42,47.69 v1(44.42,47.57) ; C88.2 43.64,47.14 ; C101.2 C105.2 v1(83.13,39.98) C104.2 C100.2 ; C101.2 82.23,41.84 ; C101.2 v1(83.13,41.25) C100.2 ; J2.14 65.48,20.37 ; J2.14 64.39,19.28 ; J2.14 66.57,19.28 ; U22.3 91.7,46.65 ; C110.2 114.08,37.55 ; C110.2 112.9,37.55 ; C110.2 v1(113.49,36.8) ; v1(50.32,51.92) R94.1 49.43,52.5 ; C77.2 16.92,52.17 ; TP12.1 52.91,44.88 ; TP12.1 51.82,43.79 ; TP12.1 52.91,42.7 ; TP12.1 54,43.79 ; 21.17,25.7 C135.2 ; C135.2 21.17,27.51 ; C135.2 22.17,26.6 ; C135.2 20.16,26.6 ; C99.2 93.76,40.74 ; C99.2 93.17,40.16 ; C99.2 92.58,40.74 ; C138.2 38.6,26.25 ; C138.2 37.59,27.15 ; C138.2 36.59,26.25 ; C92.2 6,44.16 ; C92.2 v1(5.41,43.28) ; C92.2 4.82,44.16 ; 44.79,45.36 C90.1 ; C90.1 44.79,46.54 ; C90.1 45.37,45.95 ; R65.2 20.55,9.35 v1(21.03,9.84) ; TVS4.A v1(71.86,5.84) ; TVS4.A 72.48,5.16 ; TVS4.A 71.86,4.62 ; TVS4.A 71.23,5.16 ; 85.47,57.17 J27.4 ; J27.4 86.53,58.23 ; 125.07,43.1 125.07,42.54 J25.2 ; C79.2 16.92,50.93 ; R76.1 107.89,60.19 ; R76.1 107.32,60.78 ; R76.1 107.32,59.6 ; 114.71,64.89 R69.2 ; R69.2 115.3,64.31 ; R69.2 115.89,64.89 ; R184.1 9.43,8.61 ; R184.1 8.84,8.03 ; R184.1 8.25,8.61 ; C50.2 116.75,63.4 ; C50.2 116.16,62.82 ; C50.2 117.35,62.82 ; 22.34,26.6 C134.2 ; C134.2 23.34,25.7 ; C134.2 23.34,27.51 ; C134.2 24.35,26.6 ; 76.38,33.21 C27.1 ; C27.1 76.38,34.93 ; C27.1 75.4,34.07 ; 37.41,50.44 R98.1 ; R98.1 37.41,51.62 ; R98.1 36.83,51.03 ; R125.1 47.75,43.41 v1(47.99,43.17) ; R125.1 47.08,43.42 C91.2 47.65,44.68 ; 19.09,52.83 C69.2 ; C69.2 C68.2 ; 123.92,39.51 J25.6 ; C129.2 50.07,30.85 ; C129.2 v1(49.48,31.6) ; C129.2 48.89,30.85 ; C132.2 42.39,26.01 v1(42.44,26.06) ; R79.2 75.62,57.73 ; R79.2 75.04,57.13 ; R79.2 v1(75.04,58.49) ; C130.2 35.13,29.27 ; C130.2 35.13,27.96 v1(35.56,27.53) ; C130.2 34.54,28.68 ; v1(114,45.23) C95.2 ; C95.2 113.4,44.44 ; C95.2 114.59,44.44 ; 95.34,58.86 C57.2 v1(96.21,58.14) ; C148.1 7.77,4.93 ; C148.1 8.36,4.36 ; C148.1 7.18,4.36 ; C61.1 77.9,57.47 ; C61.1 v1(77.32,58.31) ; C61.1 77.32,56.88 ; R121.2 7.27,44.16 ; R121.2 v1(6.68,43.28) ; R121.2 6.09,44.16 ; v1(95.73,49.47) 95.48,49.72 C81.1 ; 41.19,31.12 C122.2 ; C122.2 41.78,31.7 ; C122.2 42.37,31.12 ; 55.36,59.03 C56.1 ; C56.1 v1(55.96,59.89) ; 77.83,39.57 77.83,40.55 v1(77.8,40.58) ; 39.19,37.11 C107.2 ; C107.2 38.6,37.69 ; C107.2 39.78,37.69 ; U27.5 68.09,24.42 v1(68.4,24.74) 68.07,25.07 U27.6 65.25,25.07 ; U27.5 66.31,23.97 ; U27.5 65.25,24.42 ; 70.91,23.97 U27.4 72.08,24.42 v1(72.11,24.45) ; 123.92,42.05 J25.2 ; J25.2 J25.4 123.92,40.78 ; C85.2 86.69,48.83 ; 78.25,41.23 C98.2 78.84,41.22 79.1,40.96 79.1,40.45 ; R140.1 v1(24.87,35.65) ; R140.1 24.87,37.02 ; R140.1 25.43,36.42 ; TP30.1 25.28,57.78 ; TP30.1 23.54,57.78 ; TP30.1 24.41,56.91 ; TP30.1 24.41,58.65 ; C102.1 15.37,40.49 v1(15.85,40.96) ; C102.1 14.95,39.9 ; C102.1 14.95,41.08 ; 129.34,58.81 U11.2 128.49,57.85 ; v1(69.7,50.11) 69.95,50.36 C80.1 ; 39.87,37.68 C106.2 ; C106.2 40.46,37.11 ; C106.2 41.05,37.68 ; 88.68,47.87 R107.2 88.09,48.63 v1(88.44,48.99) ; 102.35,61.17 C51.2 ; C51.2 103.35,60.44 103.63,60.16 103.71,60.16 103.75,60.13 103.71,60.13 103.71,60.09 103.76,60.09 v1(103.84,60.01) ; C51.2 104.36,61.17 ; C51.2 103.35,62.08 ; 36.49,26.25 C139.2 35.48,27.15 ; C100.2 84.04,41.84 ; 70.83,49.77 C80.1 ; C80.1 70.83,50.95 ; 37.48,34.71 C116.2 ; C116.2 38.05,35.31 ; C116.2 37.48,35.9 ; 123.92,38.24 J25.8 ; 5.61,5.16 TVS5.1 ; TVS5.1 6.1,5.94 ; TVS5.1 6.58,5.16 ; TVS5.1 6.1,4.38 ; 65.48,40.69 J5.6 66.57,39.6 ; 20.35,52.83 C68.2 ; C68.2 20.94,53.41 ; 6.15,54.86 5.56,54.86 J10.B12 ; C124.2 45.92,31.68 ; 125.55,36.37 J25.10 ; J25.10 127.15,36.97 ; J25.10 123.92,36.97 ; v1(78.08,54.93) U15.2 80.11,54.93 ; 20.68,5.06 R68.1 ; R68.1 20.68,6.25 ; R68.1 21.26,5.66 ; C103.2 103.33,35.91 ; C103.2 103.33,33.75 ; C103.2 v1(100.41,34.83) ; C103.2 v1(106.02,34.83) ; R204.1 64.97,51.88 ; R204.1 64.39,51.29 ; R204.1 64.39,52.48 ; 47.48,3.76 Q3.1 v1(49.68,3.76) ; U21.2 74.63,47.55 v1(74.86,47.78) ; J9.1 4.74,4.9 ; J9.1 3.51,6.13 ; J9.1 2.27,4.9 ; C143.1 28.84,19.97 ; C143.1 28.84,18.79 ; C143.1 28.27,19.38 ; 49.08,23.82 U28.H 50.44,23.82 ; v1(47.96,30.71) 48.64,30.71 ; 77.57,2.1 J11.7 ; 76.3,2.1 J11.5
  BOTTOM w0.508: U18.2 93.01,53.66 ; R101.1 91.64,49.99 91.19,49.53 ; v1(98.71,52.36) U20.3 98.71,54.71 R86.1 ; C98.2 78.82,41.22 v1(78.08,41.22) ; C125.2 C124.2
  vias: v1(1.57,62.18) v1(1.8,67.69) v1(1.9,7.01) v1(2.03,50.44) v1(2.06,53.8) v1(2.41,42.95) v1(4.75,61.11) v1(7.34,48.33) v1(7.44,7.72) v1(7.44,6.45) v1(7.44,5.31) v1(8.48,65.81) v1(8.46,61.39) v1(8.48,5.4) v1(8.59,12.55) v1(8.59,6.45) v1(8.66,18.29) v1(8.69,2.05) v1(8.84,7.72) v1(9.86,40.79) v1(10.24,7.72) v1(10.36,13.56) v1(10.36,12.55) v1(11.46,2.02) v1(12.19,69.56) v1(14.81,17.73) v1(15.16,67.79) v1(15.47,2.25) v1(17.22,52.43) v1(17.22,51.03) v1(18.19,14.86) v1(18.87,52.43) v1(18.87,51.03) v1(18.87,49.76) v1(19.46,14.39) v1(20.4,52.43) v1(20.4,51.03) v1(20.4,49.76) v1(20.65,27.79) v1(21.14,42.27) v1(21.59,6.65) v1(21.79,27.79) v1(21.97,69.49) v1(23.32,27.79) v1(23.77,56.33) v1(23.83,14.29) v1(24.13,11.57) v1(24.46,27.79) v1(25.12,45.53) v1(25.73,27.79) v1(25.91,7.32) v1(27.33,19.6) v1(27.53,9.34) v1(27.94,19.27) v1(29.64,69.49) v1(30.66,57.27) v1(30.84,9.34) v1(32.59,7.19) v1(33.15,40.73) v1(33.2,41.57) v1(33.35,43.28) v1(33.35,4.92) v1(35.03,9.34) v1(35.66,42.73) v1(35.92,6.07) v1(36.04,54.93) v1(36.04,53.66) v1(36.2,2.28) v1(36.3,51.5) v1(36.53,27.53) v1(37.03,58.21) v1(38.18,36.8) v1(38.18,31.85) v1(38.18,27.53) v1(39.07,27.53) v1(39.73,2.15) v1(39.83,36.8) v1(39.83,35.15) v1(39.83,33.5) v1(41.48,35.15) v1(41.48,33.5) v1(41.48,31.85) v1(42.85,2.1) v1(43.05,51.26) v1(43.13,36.8) v1(45.21,46.96) v1(47.7,16.4) v1(47.68,13.3) v1(47.98,26.23) v1(48.44,36.52) v1(48.87,26.23) v1(50.01,10.86) v1(50.24,14.04) v1(50.32,28.78) v1(51.03,54.42) v1(51.59,41.88) v1(51.66,24.83) v1(51.66,10.99) v1(52.17,13.15) v1(52.43,25.98) v1(53.14,60.65) v1(53.54,29.03) v1(53.57,31.17) v1(54.03,10.44) v1(54.84,24.83) v1(55.6,13.15) v1(55.73,9.27) v1(55.85,25.98) v1(56.52,43.4) v1(57.89,24.71) v1(58.39,10.51) v1(58.55,43.43) v1(58.9,25.98) v1(59,60.5) v1(59.41,49.62) v1(60.3,24.71) v1(60.68,31.31) v1(60.76,47.59) v1(61.8,48.96) v1(61.95,60.9) v1(62.33,34.1) v1(62.33,32.58) v1(62.46,27.5) v1(63.47,35.25) v1(63.86,30.68) v1(64.69,35.63) v1(64.87,54.17) v1(64.95,47.19) v1(65.13,63.31) v1(65.63,30.68) v1(66.34,51.15) v1(66.27,30.68) v1(67.13,4.79) v1(67.41,41.33) v1(67.54,44.01) v1(67.67,52.39) v1(67.92,10.23) v1(68.76,1.9) v1(68.94,32.45) v1(68.86,3.6) v1(69.24,55.39) v1(69.52,46.96) v1(70.34,33.47) v1(70.84,55.44) v1(71.88,1.82) v1(72.14,45) v1(72.15,38.76) v1(72.36,55.49) v1(73,12.13) v1(74.27,32.07) v1(74.65,68.01) v1(74.65,66.87) v1(78.18,57.39) v1(78.71,14.17) v1(78.94,48.9) v1(79.86,67.76) v1(81.33,9.72) v1(82.35,4.89) v1(82.55,53.49) v1(83.46,10.38) v1(84.18,63.19) v1(85.04,2.05) v1(85.14,12.62) v1(86.79,8.48) v1(88.21,67.53) v1(89.26,61.41) v1(89.38,59.89) v1(90.53,59.76) v1(92.56,51.88) v1(92.66,64.61) v1(93.27,11.96) v1(93.29,8.37) v1(93.32,5.35) v1(93.29,1.49) v1(93.37,39.84) v1(93.47,54.2) v1(93.52,14.8) v1(94.21,44.65) v1(96.32,63.47) v1(96.9,2.89) v1(96.9,1.64) v1(96.98,4.36) v1(97.92,69.41) v1(103.48,39.87) v1(107.21,57.35) v1(108.15,59.84) v1(110.01,43.38) v1(110.21,63.39) v1(110.95,57.27) v1(111.66,63.26) v1(112.04,61.23) v1(112.14,45.94) v1(112.17,48.1) v1(112.47,62.07) v1(112.7,64.74) v1(113.41,51.15) v1(113.51,56.41) v1(113.48,40.01) v1(114.07,61.43) v1(114.2,63.77) v1(114.17,53.28) v1(115.11,62.07) v1(115.11,60.75) v1(115.11,59.78) v1(115.16,63.31) v1(115.24,55.54) v1(115.29,58.72) v1(115.29,57.68) v1(115.34,56.71) v1(115.29,54.68) v1(115.29,53.71) v1(115.67,61.54) v1(116.03,63.7) v1(116.69,64.08) v1(116.69,46.47) v1(117.45,36.77) v1(117.59,68.39) v1(117.65,66.21) v1(117.7,69.92) v1(117.78,63.82) v1(118.11,62.15) v1(118.16,67.25) v1(118.57,68.95) v1(118.85,41.22) v1(119.02,69.94) v1(119.1,65.68) v1(119.76,67.58) v1(120.04,63.04) v1(120.32,59.15) v1(120.9,64.64) v1(120.88,35.88) v1(121.13,69.87) v1(121.08,68.04) v1(121.11,66.18) v1(121.31,61.43) v1(121.26,60.16) v1(121.67,63.59) v1(121.92,34.16) v1(122.25,64.53) v1(122.73,54.32) v1(122.96,69.87) v1(122.96,68.72) v1(122.99,67.33) v1(123.09,63.01) v1(123.14,61.54) v1(123.14,60.24) v1(123.09,55.19) v1(123.09,35.12) v1(123.16,66.24) v1(123.27,53.05) v1(123.34,42.21) v1(123.42,65.27) v1(123.57,38.78) v1(123.67,52.19) v1(123.9,63.82) v1(124.18,54.3) v1(124.28,53.03) v1(124.56,55.19) v1(124.66,35.2) v1(124.69,34.1) v1(124.94,66.92) v1(125.04,63.87) v1(125.09,61.82) v1(125.83,69.61) v1(125.76,62.58) v1(125.86,68.6) v1(126.09,63.85) v1(126.46,57.35) v1(126.59,66.79) v1(126.57,62.2) v1(126.64,56.74) v1(126.92,65.65) v1(126.92,63.85) v1(127.64,55.52) v1(127.66,62.22) v1(127.97,66.87) v1(128.24,52.77) v1(128.35,69.36) v1(128.27,63.85) v1(128.52,68.04) v1(128.55,35.1) v1(128.57,62.2) v1(128.93,32.96) v1(129.21,65.65) v1(129.39,64.08) v1(129.49,66.79) v1(129.62,62.15) v1(129.57,55.97) v1(129.67,68.06) v1(129.92,44.19) v1(130.23,65.98) v1(130.28,62.83) v1(130.43,56.13) v1(130.43,53.18) v1(130.61,64.46) v1(130.71,61.79) v1(130.68,58.97) v1(130.68,58.11) v1(130.68,57.29) v1(131.06,66.69) v1(131.14,52.54) v1(131.55,64.97) v1(131.78,61.31) v1(131.88,63.7) v1(132.31,65.4) v1(132.28,62.37) v1(132.44,55.97) v1(132.46,59.78) v1(132.51,58.13) v1(132.79,60.83) v1(132.82,57.12) v1(132.97,58.82) v1(133.15,64.38) v1(133.48,56.25) v1(133.68,61.99) v1(134.16,63.49) v1(134.24,57.52) v1(134.26,59.61) v1(134.42,61) v1(134.7,62.93) v1(134.82,55.92) v1(135.41,62.22) v1(135.41,55.34) v1(135.51,60.6) v1(135.46,58.34) v1(135.56,52.52) v2(78.21,37.41) v2(78.71,37.41) v2(79.2,36.04) v2(79.2,34.77)
GND_EARTH1: length 11.4
  BOTTOM w0.381: J28.SH2 103.05,67.85 ; J28.SH2 102.27,66.57 ; J28.SH2 103.83,66.57 ; J28.SH4 103.83,69.57 ; J28.SH4 102.27,69.57 ; J28.SH4 103.05,68.29 ; 112.25,68.29 J28.SH3 ; J28.SH3 111.47,69.57 ; J28.SH3 113.03,69.57 ; J28.SH1 113.03,66.57 ; J28.SH1 111.47,66.57 ; J28.SH1 112.25,67.85
GND_EARTH2: length 10.4
  BOTTOM w0.381: 93.81,60.94 J27.5 95.54,62.67 ; 80.67,60.94 J27.6 ; J27.6 82.4,62.67 ; J27.6 84.13,60.94 ; J27.6 82.4,59.21
GND_EARTH3: length 24
  TOP w0.381: 4.65,46.83 J10.SH2 ; J10.SH2 3.37,47.62 ; J10.SH2 4.65,48.4 ; 1.65,56.03 J10.SH3 ; J10.SH3 2.93,56.82 ; J10.SH3 1.65,57.6 ; 4.65,56.03 J10.SH1 ; J10.SH1 4.65,57.6 ; J10.SH1 3.37,56.82 ; J10.SH4 2.93,47.62 ; J10.SH4 1.65,46.83 ; J10.SH4 1.65,48.4
  BOTTOM w0.381: J10.SH4 2.93,47.62 ; J10.SH4 1.65,46.83 ; J10.SH4 1.65,48.4 ; J10.SH1 4.65,57.6 ; J10.SH1 3.37,56.82 ; J10.SH1 4.65,56.03 ; J10.SH2 5.93,47.62 ; J10.SH2 3.37,47.62 ; J10.SH2 4.65,48.4 ; J10.SH2 4.65,46.83 ; 1.65,56.03 J10.SH3 ; J10.SH3 1.65,57.6 ; J10.SH3 2.93,56.82
VBAT: length 8.6
  L06_SIG w0.381: J15.1 11.59,65.9 ; J15.1 11.59,64.04 ; J15.1 10.66,64.97 ; J15.1 12.52,64.97
  BOTTOM w0.203: U19.8 43.81,48.91 C88.1 43.31,49.08 U19.9
  BOTTOM w0.381: v1(44.4,48.74) C88.1 43.64,48.74 v1(42.88,48.74)
VBAT_PP: length 1.7
  TOP w0.381: D1.A 42.14,56.97 v1(42.01,57.09)
  vias: v1(40.59,57) v1(44.91,50.52) v1(45.54,49.89)
VBUS_DEV: length 7.7
  TOP w0.254: J28.B9 108.9,65.77 J28.A4 ; J28.A9 106.4,65.77 J28.B4
  L03_SIG w0.381: 106.45,65.27 J28.B4 105.9,65.82 ; 108.85,65.27 J28.B9 109.41,65.82
  L04_MIX w0.381: 106.45,65.27 J28.B4 105.9,65.82 ; 108.85,65.27 J28.B9
  BOTTOM w0.381: 105.9,65.82 J28.B4 106.45,65.27
  vias: v1(92.81,51.12) v1(93.57,51.12) v1(100,62.12) v1(100.91,61.69) v1(100.9,60.7) v1(104.65,63.49) v1(105.69,63.49) v1(106.48,63.57)
VBUS_DISCHARGE: length 2.9
  TOP w0.203: 16.74,47.12 U3.32
  TOP w0.381: v1(16.51,45.26) 16.51,45.85 v1(16.59,45.92) 16.74,46.07 16.74,47.12
VBUS_HOST: length 11.3
  L06_SIG w0.381: J27.1 92.47,59.29 ; J27.1 91.42,58.23 ; J27.1 93.53,58.23
  BOTTOM w0.381: 91.42,58.23 J27.1 ; J27.1 93.53,58.23 ; J27.1 92.47,57.17
  BOTTOM w0.508: C66.1 81,56.39 v1(81,56.94) ; C66.1 82.58,56.01 v1(82.91,56.33) ; C66.1 81.26,55.88 U15.1
VBUS_P_CTRL0: length 20.1
  TOP w0.114: v1(24.13,45.69) 24.13,48.18 22.98,49.33 U3.2
  L03_SIG w0.114: v1(24.64,34) 24.13,34.51 v1(24.13,45.69)
  BOTTOM w0.114: v1(24.64,34) 24.54,34.11 R144.2 23.11,34.11 R143.1
VBUS_P_CTRL1: length 16.1
  TOP w0.114: v1(22.76,47.8) 22.76,48.4 22.33,48.83 U3.1
  L06_SIG w0.114: v1(22.76,47.8) 23.47,47.08 23.47,44.82 22,43.35 v1(21.16,43.35)
  BOTTOM w0.114: R137.1 22.85,38.74 R138.1 21.94,38.58 21.94,39.57 20.52,40.98 20.52,42.72 v1(21.16,43.35)
VBUS_TC: length 11.9
  TOP w0.254: J10.B9 5.45,53.47 J10.A4 7.65,53.47 v1(7.72,53.54)
  TOP w0.305: J10.B4 5.45,50.97 J10.A9 7.5,50.97 7.85,50.61
  TOP w0.381: v1(13.51,46.27) 13.4,46.16 R26.1 ; R7.1 v1(11.05,52.02)
  TOP w0.457: v1(8.48,49.47) 8.48,49.98 7.85,50.61
  BOTTOM w0.381: 5.4,50.46 J10.B4 5.96,51.02 ; 5.4,53.97 J10.B9 5.96,53.42 ; v1(11.05,52.02) 11.05,50.49
  vias: v1(25.37,48.07) v1(25.37,47.31) v1(26.25,46.18) v1(26.52,48.07) v1(26.52,47.31) v1(29.49,44.57) v1(30.33,45.28) v1(37.44,21.53) v1(38.2,21.53) v1(38.86,21.53) v1(46.71,46.8) v1(47.35,46.8)
VBUS_TC_MON: length 5.4
  TOP w0.114: C10.1 12.83,54.7 R3.2 12.84,53.35 R7.2 13.03,51.83 U3.24
VCC_1V8: length 2
  BOTTOM w0.381: R103.2 97.37,49.74 96.81,50.29 U20.5
  vias: v1(72.11,53.28) v1(72.11,52.39) v1(95.73,51.5) v1(95.78,50.74)
VCC_3V3: length 59.8
  TOP w0.305: U4.B4 v1(112.48,39.22)
  TOP w0.381: v1(33.35,42.51) 32.88,42.51 29.84,39.48 29.84,35.22 28.73,34.1 27.13,34.1 25.71,32.68 25.71,29.23 26.49,28.45 26.49,27.48 26.2,27.18 R57.1 ; TP9.1 59.49,47.82 ; TP9.1 58.39,46.73 ; TP9.1 57.57,48.65 56.05,48.65 54.08,46.68 49.02,46.68 48.02,47.68 v1(47.15,47.68) ; TP9.1 57.3,47.82 ; TP9.1 58.39,48.91
  L03_SIG w0.381: v1(33.35,42.51) 33.81,42.51 39.62,48.33 41.88,48.33 44.04,46.17 45.69,46.17 45.95,46.42 45.95,46.93 46.7,47.68 v1(47.15,47.68)
  BOTTOM w0.203: C65.1 87.63,54.33 U16.9
  BOTTOM w0.254: v1(50.82,22.72) 50.62,22.92 U28.3 ; U28.1 v1(48.97,24.72)
  vias: v1(57.25,34.87) v1(58.01,34.87) v1(87.48,59.76) v1(88.1,55.98) v1(88.24,59.76) v1(88.86,55.98) v1(110.31,39.14) v1(111.23,39.13) v1(133.07,51.94) v1(133.68,51.1) v1(134.34,51.91)
VCC_5V: length 19.6
  TOP w0.381: v1(41.22,54.2) 40.97,53.95 R5.2 ; v1(41.22,54.2) v1(40.75,54.68) ; v1(41.22,54.2) 41.48,53.95 D2.A ; R6.2 37.29,53.06 v1(37.41,53.19) ; 66.02,32.65 C39.1 66.78,31.89 ; v1(101.12,58.74) 101.65,59.28 R197.2 ; v1(37.12,54.93) 37.37,55.17 R1.2
  L05_MIX w0.381: 20.14,31.5 TP27.1 ; TP27.1 21.23,32.59 ; TP27.1 20.14,33.68 ; TP27.1 19.05,32.59
  BOTTOM w0.381: v1(18.26,32.83) 18.51,32.59 TP27.1 ; U15.5 76.43,57.35 C61.2 v1(76.3,58.34) ; 20.14,31.5 TP27.1 ; TP27.1 21.23,32.59
  vias: v1(18.26,31.95) v1(41.82,46.33) v1(42.83,46.33) v1(59.79,30.29) v1(62.71,30.42) v1(62.71,24.71) v1(62.71,23.56) v1(62.97,22.29) v1(65.13,31.56) v1(65.89,31.56) v1(66.65,31.56) v1(75.39,51.41) v1(75.39,50.27) v1(92.56,56.33) v1(93.32,56.46)
VCC_IO_FLASH: length 0.8
  TOP w0.305: U4.E4 v1(112.87,43.41)
VCC_VAR: length 4.4
  TOP w0.381: U10.5 63.54,29.73 63.8,29.98 R50.2
  vias: v1(48.62,34.64) v1(49.38,34.61) v1(49.99,27.15) v1(49.99,26.14)
VCCD: length 15.7
  TOP w0.203: U1.A2 v2(87.32,44.02)
  L03_SIG w0.305: v2(87.32,44.02) 88.11,44.02
  L03_SIG w0.381: TP6.1 90.2,47.44 89.61,46.86 89.61,45.52 88.11,44.02
  BOTTOM w0.254: R129.2 84.53,42.65 84.79,42.9 88.09,42.9 88.34,43.15 C93.1 87.54,43.81 v2(87.32,44.02)
